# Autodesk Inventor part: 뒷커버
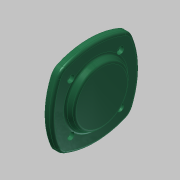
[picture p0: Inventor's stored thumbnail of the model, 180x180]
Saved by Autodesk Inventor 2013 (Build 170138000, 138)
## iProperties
Created: 2015-11
Part Number: 뒷커버
Material: 일반
Document SubType Name: Modeling
Designer: mduedu
Density: 1 g/cm^3
Mass: 120.056 g
Surface Area: 247.583 cm^2
Volume: 120.056 cm^3
Author: mduedu
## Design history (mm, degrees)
sketch "스케치1"
  geometry: L1 (50, 50)-(-50, 50); L2 (-50, 50)-(-50, -50); L3 (-50, -50)-(50, -50); L4 (50, -50)-(50, 50); L5 (0, 50)-(0, -50); L6 (50, 0)-(-50, 0); A1 r 90 centre (-40, 0) between (40.415, -40.415) and (40.415, 40.415); A2 r 90 centre (40, 0) between (-40.415, 40.415) and (-40.415, -40.415); A3 r 90 centre (0, -40) between (40.415, 40.415) and (-40.415, 40.415); A4 r 90 centre (0, 40) between (-40.415, -40.415) and (40.415, -40.415); 2 further points
  constraints: 12 end point, 8 point on circle, 5 midpoint, 4 centre point, 2 horizontal alignment, 2 parallel, 2 perpendicular, 2 symmetric about line, 2 tangent, 2 vertical alignment, 1 equal radius, 1 horizontal, 2 other
  dimensions: "d0" = 100 distance of L3.end L1.start; "d2" = 90 radius of A1
extrude "돌출1" new body sketch "스케치1" distance "d3" = 8; taper "d4" = 0 deg
sketch "스케치2"
  geometry: C1 r 35 at (0, 0); 1 further point
  constraints: 1 centre point, 1 coincident
  dimensions: "d5" = 70 diameter of C1
extrude "돌출2" join sketch "스케치2" distance "d6" = 7; taper "d7" = -30 deg
sketch "스케치3"
  geometry: L1 (0, 0)-(0, 40); L2 (0, 0)-(-28.284, 28.284); A1 r 40 centre (0, 0) between (0, 40) and (-28.284, 28.284); 2 further points
  constraints: 4 end point, 2 coincident, 2 point on circle, 1 centre point, 1 vertical
  dimensions: "d8" = 80 diameter of A1; "d9" = 45 deg angle of L1 L2
hole "구멍1" sketch "스케치3" at (-28.284, 28.284) diameter "d11" = 4.5; stored, may be unused: countersink angle "d15" = 90 deg, drill point angle "d17" = 118 deg; dims "d12" = 6, "d13" = 8, "d14" = 4.4, "d16" = 8
sketch "스케치4"
  geometry: C1 r 35 at (0, 0); 1 further point
  constraints: 1 centre point, 1 coincident
  dimensions: "d21" = 70 diameter of C1
extrude "돌출3" join sketch "스케치4" distance "d23" = 12; taper "d24" = 0 deg
hole "구멍2" diameter "d27" = 30; stored, may be unused: countersink angle "d31" = 90 deg, drill point angle "d33" = 0 deg; dims "d25" = 10, "d26" = 10, "d28" = 6, "d29" = 40, "d30" = 12, "d32" = 15
fillet "모깎기2" dims "d35" = 15
fillet "모깎기3" dims "d36" = 3
fillet "모깎기4" dims "d37" = 3
fillet "모깎기5" dims "d38" = 0.3
chamfer "모따기1" distance "d39" = 1; stored, may be unused: second distance "d40" = 2, angle "d41" = 45 deg
node "솔리드1"
pattern_circular "원형 패턴1" dims angle "d19" = 360 deg
